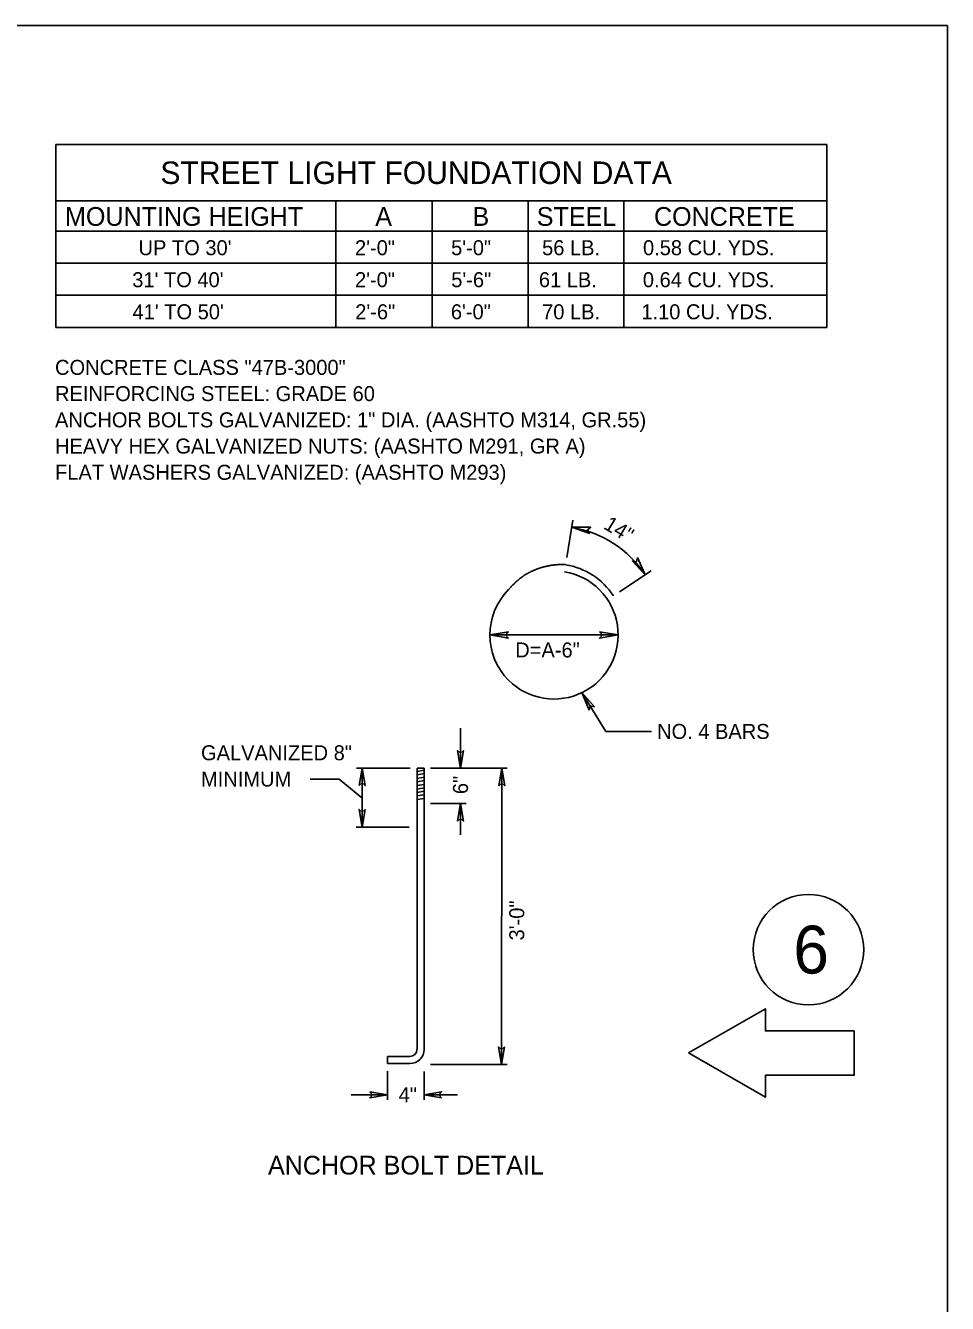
# Model space of a CAD drawing. Extents: x 99836 to 115004, y 99786 to 102182.
# Drawn here: x 107532 to 108270, y 101063 to 102086 of the extents above; entities that cross this region are included whole.
import ezdxf

# ---------------------------------------------------------------- set-up
doc = ezdxf.new("R2010")
doc.units = 0
for name, color, linetype in [('Border Organizer Shape', 7, 'Continuous'), ('Default', 7, 'Continuous'), ('Notes General Notes', 7, 'Continuous')]:
    doc.layers.add(name, color=color, linetype=linetype)

msp = doc.modelspace()

# ---------------------------------------------------------------- linework, layer by layer
at = {"layer": 'Border Organizer Shape'}
for p, q in [((107556.2, 101990.4), (108173, 101990.4)), ((107556.2, 101844.1), (107556.2, 101990.4)), ((108173, 101844.1), (108173, 101990.4)), ((107556.2, 101945.4), (108173, 101945.4)), ((107780.3, 101844.1), (107780.3, 101945.4)), ((107857.4, 101844.1), (107857.4, 101945.4)), ((107934.1, 101844.1), (107934.1, 101945.4)), ((108010.7, 101844.1), (108010.7, 101945.4)), ((107556.2, 101921.1), (108173, 101921.1)), ((107556.2, 101895.4), (108173, 101895.4)), ((107556.2, 101869.8), (108173, 101869.8)), ((107556.2, 101844.1), (108173, 101844.1)), ((107965, 101659.8), (107970, 101689.7)), ((108007.3, 101632.5), (108032.6, 101649.2)), ((107903.5, 101597.9), (108006.1, 101597.9)), ((107880.1, 101491.3), (107880.1, 101523.2)), ((107782.9, 101482.6), (107759.6, 101482.6)), ((107782.9, 101482.6), (107801.1, 101467.6)), ((107839.6, 101491.4), (107796.7, 101491.4)), ((107801.2, 101444.1), (107801.2, 101491.4)), ((107845.2, 101491.3), (107845.2, 101472.4)), ((107850.9, 101491.3), (107845.2, 101491.3)), ((107850.9, 101489.6), (107845.2, 101488.7)), ((107850.9, 101486.9), (107845.2, 101485.9)), ((107850.9, 101484.1), (107845.2, 101483.1)), ((107850.9, 101491.3), (107850.9, 101472.4)), ((107917.4, 101491.3), (107856, 101491.3)), ((107912.9, 101254.1), (107913, 101491.3)), ((107850.8, 101475.6), (107845.1, 101474.6)), ((107850.8, 101481.3), (107845.2, 101480.3)), ((107850.8, 101478.3), (107845.2, 101477.4)), ((107850.8, 101472.8), (107845.2, 101471.8)), ((107845.2, 101472.4), (107845.2, 101266.2)), ((107850.9, 101472.4), (107850.9, 101266.2)), ((107850.7, 101470), (107845.2, 101469.1)), ((107850.7, 101467), (107845.2, 101466.1)), ((107884.6, 101463), (107856, 101463)), ((107880, 101437.9), (107880, 101463)), ((107839, 101444.1), (107796.6, 101444.1)), ((107821.5, 101260.5), (107839.5, 101260.5)), ((107821.5, 101260.5), (107821.5, 101254.8)), ((107821.5, 101254.8), (107839.5, 101254.8)), ((107821.5, 101225.9), (107821.5, 101248.7)), ((107850.8, 101225.8), (107850.9, 101248.6)), ((107917.3, 101254.1), (107855.9, 101254.2)), ((107821.5, 101229.9), (107792.6, 101229.9)), ((107877.5, 101229.9), (107850.8, 101229.9))]:
    msp.add_line(p, q, dxfattribs=at)
for points in [[(107983.4, 101679.2), (107969.1, 101684.1), (107984.2, 101684.1), (107981.5, 101682.1)], [(108021.6, 101659.8), (108027.7, 101646), (108017.5, 101657.1), (108020.8, 101656.5)], [(107918.3, 101595.4), (107903.5, 101597.9), (107918.3, 101600.4), (107916, 101597.9)], [(107991.2, 101600.4), (108006.1, 101597.9), (107991.2, 101595.4), (107993.6, 101597.9)], [(107982.9, 101537.8), (107977.2, 101551.8), (107987.1, 101540.4), (107983.8, 101541.1)], [(107882.5, 101505.4), (107880.1, 101491.3), (107877.7, 101505.4), (107880.1, 101503.2)], [(107798.8, 101477.3), (107801.2, 101491.4), (107803.6, 101477.3), (107801.2, 101479.5)], [(107910.6, 101477.2), (107913, 101491.3), (107915.4, 101477.2), (107913, 101479.4)], [(107877.6, 101448.9), (107880, 101463), (107882.4, 101448.9), (107880, 101451.1)], [(107803.6, 101458.2), (107801.2, 101444.1), (107798.8, 101458.2), (107801.2, 101456)], [(107915.3, 101268.2), (107912.9, 101254.1), (107910.5, 101268.2), (107912.9, 101266)], [(107807.4, 101232.3), (107821.5, 101229.9), (107807.4, 101227.5), (107809.6, 101229.9)], [(107864.9, 101227.5), (107850.8, 101229.9), (107864.9, 101232.3), (107862.7, 101229.9)]]:
    msp.add_lwpolyline(points, close=True, dxfattribs=at)
msp.add_lwpolyline([(107977.2, 101551.8), (107996.3, 101520.7), (108032.8, 101520.7)], dxfattribs=at)
for centre, radius, start, end in [((107954.8, 101597.9), 87.4, 33.427, 80.5536), ((107954.8, 101597.9), 51.3, 224.9925, 80.5568), ((107954.8, 101597.9), 57, 33.4279, 80.5568), ((107954.8, 101597.9), 51.3, 134.9925, 224.9925), ((107839.5, 101266.2), 5.68, 270, 360), ((107839.5, 101266.2), 11.4, 270, 360)]:
    msp.add_arc(centre, radius, start, end, dxfattribs=at)
msp.add_spline([(107964.1, 101654.2), (107963.3, 101654.2), (107962.6, 101654.2), (107961.7, 101654.2), (107960.9, 101654.2), (107960.2, 101654.2), (107959.4, 101654.2), (107958.6, 101654.2), (107957.7, 101654.2), (107957, 101654.1), (107956.2, 101654), (107955.4, 101654), (107954.5, 101653.9), (107953.8, 101653.8), (107953, 101653.7), (107952.3, 101653.6), (107951.4, 101653.4), (107950.7, 101653.3), (107949.9, 101653.1), (107949.1, 101653), (107948.3, 101652.8), (107947.5, 101652.6), (107946.8, 101652.4), (107946.1, 101652.2), (107945.2, 101652), (107944.5, 101651.8), (107943.7, 101651.6), (107943, 101651.3), (107942.2, 101651), (107941.5, 101650.8), (107940.7, 101650.5), (107940, 101650.1), (107939.2, 101649.9), (107938.5, 101649.6), (107937.8, 101649.2), (107937, 101648.9), (107936.3, 101648.5), (107935.7, 101648.1), (107934.9, 101647.8), (107934.2, 101647.4), (107933.6, 101647), (107932.8, 101646.7), (107932.1, 101646.2), (107931.5, 101645.9), (107930.8, 101645.4), (107930.2, 101644.9), (107929.5, 101644.5), (107928.8, 101644), (107928.2, 101643.6), (107927.5, 101643.1), (107926.9, 101642.6), (107926.4, 101642.1), (107925.7, 101641.6), (107925.1, 101641.1), (107924.5, 101640.6), (107923.9, 101640), (107923.4, 101639.5), (107922.8, 101638.9), (107922.3, 101638.4), (107921.6, 101637.7), (107921.1, 101637.2), (107920.6, 101636.6), (107920.1, 101636), (107919.5, 101635.4), (107919, 101634.8), (107918.5, 101634.2)], degree=3, dxfattribs=at)
at = {"layer": 'Default'}
msp.add_lwpolyline([(105069.9, 102085.7), (108269.6, 102085.7), (108269.6, 99886.1), (105069.9, 99886.1)], close=True, dxfattribs=at)
at = {"layer": 'Notes General Notes'}
msp.add_lwpolyline([(108062.5, 101263.3), (108124, 101227.8), (108124, 101245.5), (108194.9, 101245.5), (108194.9, 101281), (108124, 101281), (108124, 101298.7)], close=True, dxfattribs=at)
msp.add_circle((108158.4, 101346), 44.2, dxfattribs=at)

# ---------------------------------------------------------------- texts
at = {"layer": 'Border Organizer Shape'}
for s, height, p in [('STREET LIGHT FOUNDATION DATA', 18, (107639.9, 101958.9)), ('MOUNTING HEIGHT', 15, (107563.6, 101925.4)), ('A', 15, (107811.8, 101925.4)), ('B', 15, (107889.6, 101925.4)), ('STEEL', 15, (107941, 101925.4)), ('CONCRETE', 15, (108034.8, 101925.4)), ("UP TO 30'", 12, (107622.4, 101901.9)), ('2\'-0"', 12, (107795.6, 101901.9)), ('5\'-0"', 12, (107872.5, 101901.9)), ('56 LB.', 12, (107945.3, 101901.9)), ('0.58 CU. YDS.', 12, (108026, 101901.9)), ("31' TO 40'", 12, (107617.4, 101876.3)), ('2\'-0"', 12, (107795.6, 101876.3)), ('5\'-6"', 12, (107872.6, 101876.3)), ('61 LB.', 12, (107942.7, 101876.3)), ('0.64 CU. YDS.', 12, (108025.9, 101876.3)), ("41' TO 50'", 12, (107617.6, 101850.6)), ('2\'-6"', 12, (107795.8, 101850.6)), ('6\'-0"', 12, (107872.3, 101850.6)), ('70 LB.', 12, (107945.3, 101850.6)), ('1.10 CU. YDS.', 12, (108024.7, 101850.6)), ('CONCRETE CLASS "47B-3000"', 12, (107555.6, 101806.1)), ('REINFORCING STEEL: GRADE 60', 12, (107555.6, 101785.1)), ('ANCHOR BOLTS GALVANIZED: 1" DIA. (AASHTO M314, GR.55)', 12, (107555.6, 101764.1)), ('HEAVY HEX GALVANIZED NUTS: (AASHTO M291, GR A)', 12, (107555.6, 101743.1)), ('FLAT WASHERS GALVANIZED: (AASHTO M293)', 12, (107555.6, 101722.1)), ('GALVANIZED 8"', 12, (107672.4, 101497.6)), ('MINIMUM ', 12, (107672.4, 101476.6)), ('4"', 12, (107830.5, 101223.9)), ('ANCHOR BOLT DETAIL', 15, (107726, 101166))]:
    msp.add_text(s, height=height, dxfattribs=at).set_placement(p)
for s, rotation, p in [('14"', 328.8322, (107993.7, 101683.5)), ('D=A-6"', 359.9925, (107923.8, 101579.9)), (' NO. 4 BARS', 359.9925, (108032.8, 101514.7)), ('6"', 90, (107886, 101470.5)), ('3\'-0"', 90, (107931, 101353.4))]:
    msp.add_text(s, height=12, rotation=rotation, dxfattribs=at).set_placement(p)
at = {"layer": 'Notes General Notes'}
msp.add_text('6', height=38.3, dxfattribs=at).set_placement((108146.3, 101326.9))

doc.saveas('drawing.dxf')
